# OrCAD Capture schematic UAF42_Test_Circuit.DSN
size A; title: UAF42, UNIVERSAL ACTIVE FILTER; rev: 1.3; note: Datasheet: SBFS002B EVM: N/A
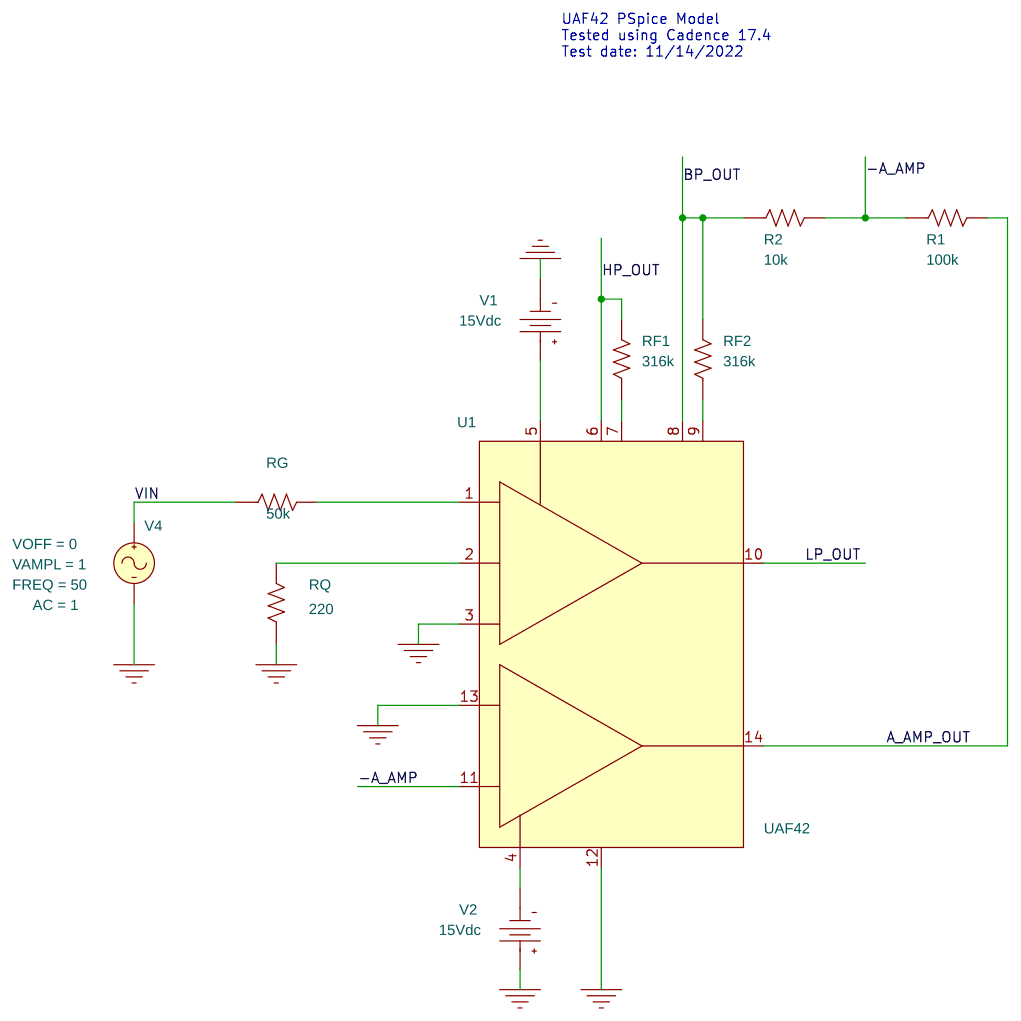
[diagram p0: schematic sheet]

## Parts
R1  100k  [AXRC05]
R2  10k  [AXRC05]
RF1  316k  [AXRC05]
RF2  316k  [AXRC05]
RG  50k  [AXRC05]
RQ  220  [AXRC05]
U1  UAF42
V1  VDC
V2  VDC
V4  VSIN

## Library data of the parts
R1 R2 RF1 RF2 RG RQ = R
U1 = UAF42
V1 V2 = VDC: DC: 15Vdc
V4 = VSIN: AC: 1; FREQ: 50; VAMPL: 1; VOFF: 0

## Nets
VIN: RG.1 V4.1(+)
0: RQ.1 U1.3(IN3) U1.12(GND) U1.13(+A_AMP) V1.1(-) V2.0(+) V4.2(-)
-A_AMP: R1.1 R2.2 U1.11(-A_AMP)
A_AMP_OUT: R1.2 U1.14(A_AMP_OUT)
BP_OUT: R2.1 RF2.2 U1.8(BP_OUT)
HP_OUT: RF1.2 U1.6(HP_OUT)
LP_OUT: U1.10(LP_OUT)
N14292818: RG.2 U1.1(IN1)
N14292854: RQ.2 U1.2(IN2)
N14296786: U1.4(V-) V2.1(-)
N14297043: U1.5(V+) V1.0(+)
N14297161: RF1.1 U1.7(FADJ1)
N14297351: RF2.1 U1.9(FADJ2)

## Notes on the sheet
- UAF42 PSpice Model
  Tested using Cadence 17.4
  Test date: 11/14/2022
